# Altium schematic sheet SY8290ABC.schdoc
size 127 x 101 mm
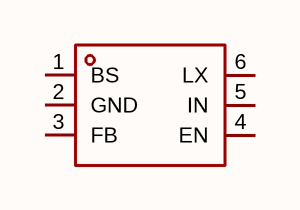
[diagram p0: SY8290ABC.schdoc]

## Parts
U?  sy8290abc  [SOT-23-6_L2.9-W1.6-P0.95-LS2.8-BL]  (value not drawn)

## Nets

Not connected (* = marked no-connect by the designer): U? 1(BS) 2(GND) 3(FB) 4(EN) 5(IN) 6(LX)

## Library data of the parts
U? = sy8290abc: 功能类型:降压型;工作电压:5V~40V;输出电压:-;输出电流:200mA;输出类型:可调;; Manufacturer: Silergy(矽力杰); AddInBom: yes; ModelId: 18da8f6c14a34920b3e136b5c401a119; ModelName: SOT-23-6_L2.9-W1.6-H1.5-LS2.8-P0.95; ModelTransform: 110.236,113.364,0,90,0,0,0.0005,0.0005,0; Function: 降压型; Voltage - Supply: 5V~40V; Output Current: 200mA; Frequency - Switching: 1.6MHz~2.4MHz; Synchronous Rectifier: 否; Number of Outputs: 1; Topology: 降压式; Quiescent Current: 160uA; Switch tube (built-in/external): 内置; Output Type: 可调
